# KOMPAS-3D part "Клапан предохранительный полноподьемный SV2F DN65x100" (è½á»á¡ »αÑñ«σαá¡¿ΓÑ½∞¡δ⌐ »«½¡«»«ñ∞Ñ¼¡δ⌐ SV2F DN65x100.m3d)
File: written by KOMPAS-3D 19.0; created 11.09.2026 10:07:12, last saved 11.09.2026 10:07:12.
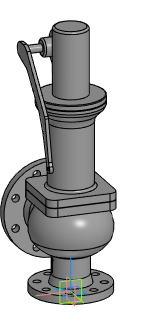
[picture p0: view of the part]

Document properties: Автор: Энергия; Полное имя файла: Z:\3.Личные\sachek\Dendor\_3D для проектировщиков\5.9 SV2F. Клапан предохранительный полноподьемный\SV2F_STP\Клапан предохранительный полноподьемный SV2F DN65x100.m3d

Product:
- Part/product: Клапан предохранительный полноподьемный SV2F DN65x100

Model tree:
1. Операция без истории:1  (labels: Клапан предохранительный полноподьемный SV2F DN65x100)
